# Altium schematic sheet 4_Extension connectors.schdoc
size 309 x 223 mm; Symbol: Artery_A4; Device: Artery_A4; Company: Artery Technology; Drawed: SD; Version: 1.1; Page Size: A4; @Project Name: p_AT-START-F437; @Page Count: 5; @Update Date: 2023-04-14 17:11:57; @Create Date: 2022-12-01; @Schematic Name: AT-START-F437 V1.1; @Page No: 4; @Page Name: Extension connectors
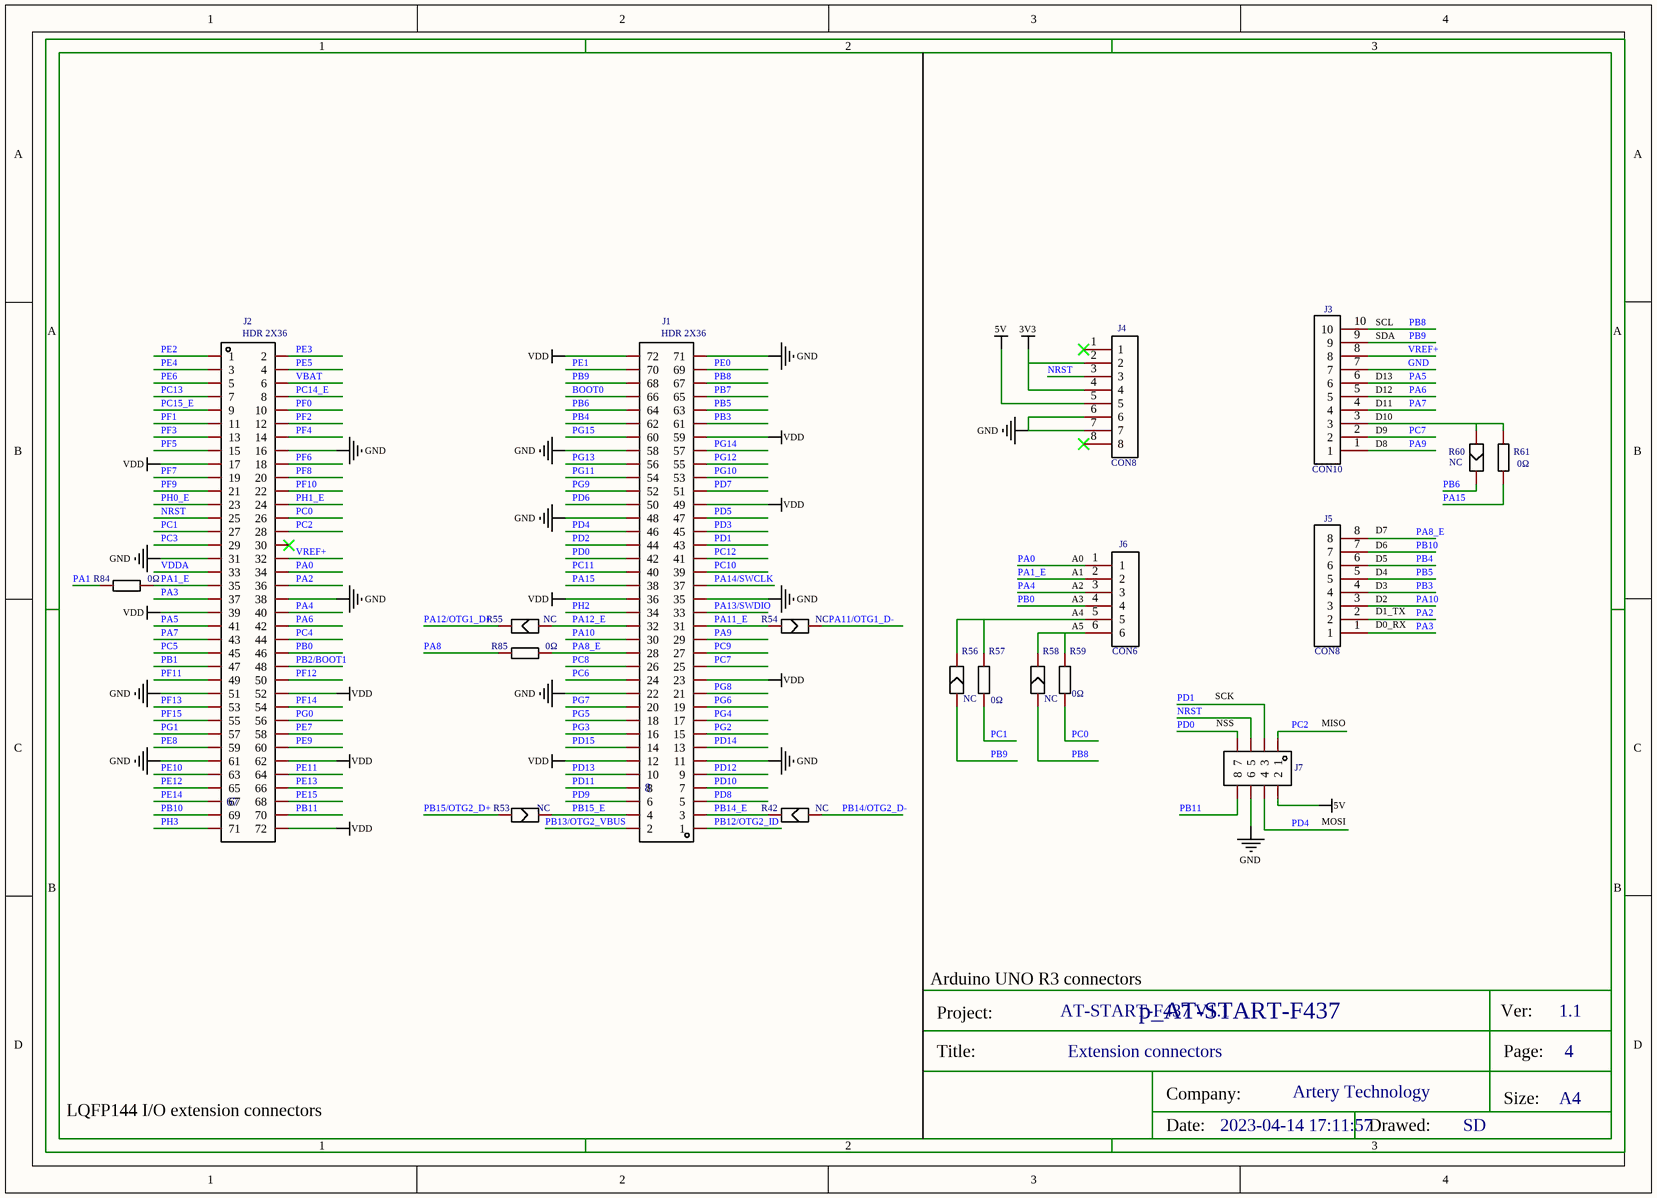
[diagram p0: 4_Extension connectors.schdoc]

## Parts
J1  NAME: 8  [HDR_2.54_2X36]  (hidden comment: HDR 2X36)
J2  NAME: 67  [HDR_2.54_2X36]  (hidden comment: HDR 2X36)
J3  CON10  [FEMALE HEADER 1X10]
J4  CON8  [FEMALE HEADER 1X8]
J5  CON8  [FEMALE HEADER 1X8]
J6  CON6  [FEMALE HEADER 1X6]
J7  Header 4X2  [HDR2X4]  (value not drawn)
R42  NC  [SB-PAD]
R53  NC  [SB-PAD]
R54  NC  [SB-PAD]
R55  NC  [SB-PAD]
R56  NC  [SB-PAD]
R57  0Ω  [R0603]
R58  NC  [SB-PAD]
R59  0Ω  [R0603]
R60  NC  [SB-PAD]
R61  0Ω  [R0603]
R84  0Ω  [R0603]
R85  0Ω  [R0603]

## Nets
3V3: J4.2 J4.4
5V: J4.5 J7.2
GND: J1.11 J1.22 J1.35 J1.48 J1.58 J1.71 J2.16 J2.31 J2.38 J2.51 J2.61 J3.7 J4.6 J4.7 J7.6
VDD: J1.12 J1.23 J1.36 J1.49 J1.59 J1.72 J2.17 J2.39 J2.52 J2.62 J2.72
BOOT0: J1.66
NRST: J2.25 J4.3 J7.5
PA0: J2.34 J6.1
PA1: R84.2
PA1_E: J2.35 J6.2 R84.1
PA2: J2.36 J5.2
PA3: J2.37 J5.1
PA4: J2.40 J6.3
PA5: J2.41 J3.6
PA6: J2.42 J3.5
PA7: J2.43 J3.4
PA8: R85.2
PA8_E: J1.28 J5.8 R85.1
PA9: J1.29 J3.1
PA10: J1.30 J5.3
PA11/OTG1_D-: R54.2
PA11_E: J1.31 R54.1
PA12/OTG1_D+: R55.2
PA12_E: J1.32 R55.1
PA13/SWDIO: J1.33
PA14/SWCLK: J1.37
PA15: J1.38 R61.1
PB0: J2.46 J6.4
PB1: J2.47
PB2/BOOT1: J2.48
PB3: J1.61 J5.4
PB4: J1.62 J5.6
PB5: J1.63 J5.5
PB6: J1.64 R60.2
PB7: J1.65
PB8: J1.67 J3.10 R58.1
PB9: J1.68 J3.9 R56.1
PB10: J2.69 J5.7
PB11: J2.70 J7.8
PB12/OTG2_ID: J1.1
PB13/OTG2_VBUS: J1.2
PB14/OTG2_D-: R42.1
PB14_E: J1.3 R42.2
PB15/OTG2_D+: R53.1
PB15_E: J1.4 R53.2
PC0: J2.26 R59.1
PC1: J2.27 R57.1
PC2: J2.28 J7.1
PC3: J2.29
PC4: J2.44
PC5: J2.45
PC6: J1.24
PC7: J1.25 J3.2
PC8: J1.26
PC9: J1.27
PC10: J1.39
PC11: J1.40
PC12: J1.41
PC13: J2.7
PC14_E: J2.8
PC15_E: J2.9
PD0: J1.42 J7.7
PD1: J1.43 J7.3
PD2: J1.44
PD3: J1.45
PD4: J1.46 J7.4
PD5: J1.47
PD6: J1.50
PD7: J1.51
PD8: J1.5
PD9: J1.6
PD10: J1.7
PD11: J1.8
PD12: J1.9
PD13: J1.10
PD14: J1.13
PD15: J1.14
PE0: J1.69
PE1: J1.70
PE2: J2.1
PE3: J2.2
PE4: J2.3
PE5: J2.4
PE6: J2.5
PE7: J2.58
PE8: J2.59
PE9: J2.60
PE10: J2.63
PE11: J2.64
PE12: J2.65
PE13: J2.66
PE14: J2.67
PE15: J2.68
PF0: J2.10
PF1: J2.11
PF2: J2.12
PF3: J2.13
PF4: J2.14
PF5: J2.15
PF6: J2.18
PF7: J2.19
PF8: J2.20
PF9: J2.21
PF10: J2.22
PF11: J2.49
PF12: J2.50
PF13: J2.53
PF14: J2.54
PF15: J2.55
PG0: J2.56
PG1: J2.57
PG2: J1.15
PG3: J1.16
PG4: J1.17
PG5: J1.18
PG6: J1.19
PG7: J1.20
PG8: J1.21
PG9: J1.52
PG10: J1.53
PG11: J1.54
PG12: J1.55
PG13: J1.56
PG14: J1.57
PG15: J1.60
PH0_E: J2.23
PH1_E: J2.24
PH2: J1.34
PH3: J2.71
VBAT: J2.6
VDDA: J2.33
VREF+: J2.32 J3.8
NetJ3_3: J3.3 R60.1 R61.2
NetJ6_5: J6.5 R56.2 R57.2
NetJ6_6: J6.6 R58.2 R59.2

Not connected (* = marked no-connect by the designer): J2 30*; J4 1* 8*

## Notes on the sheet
- (near J3) SDA
- (near J3) SCL
- (near J3) D11
- (near J3) D12
- (near J3) D13
- (near J3) D8
- (near J3) D9
- (near J3) D10
- (near J5) D7
- (near J6) A0
- (near J6) A1
- (near J6) A2
- (near J6) A3
- (near J5) D1_TX
- (near J5) D2
- (near J5) D3
- (near J5) D4
- (near J5) D5
- (near J5) D6
- A4
- A5
- (near J5) D0_RX
- (near J7) SCK
- (near J7) NSS
- (near J7) MISO
- MOSI
- Arduino UNO R3 connectors
- LQFP144 I/O extension connectors

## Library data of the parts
J1 = HDR 2X36: Convert to PCB: yes; NUMBER: 6
J2 = HDR 2X36: Convert to PCB: yes
J3 = CON10: Convert to PCB: yes
J4 J5 = CON8: Convert to PCB: yes
J6 = CON6: Convert to PCB: yes
J7 = Header 4X2: Convert to PCB: yes
R42 R53-R56 R58 R60 = NC: Convert to PCB: yes
R57 R59 R61 R84 R85 = 0603WAF0000T5E: 电阻类型:厚膜电阻;阻值:0Ω;精度:±1%;功率:100mW;最大工作电压:75V;工作温度范围:-55℃~+155℃;; Manufacturer: UNI-ROYAL(厚声); Add into BOM: yes; Tolerance: ±1%; Power(Watts): 100mW; Overload Voltage (Max): 75V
